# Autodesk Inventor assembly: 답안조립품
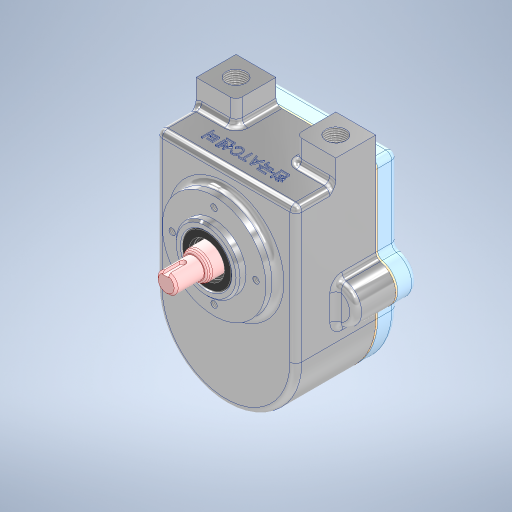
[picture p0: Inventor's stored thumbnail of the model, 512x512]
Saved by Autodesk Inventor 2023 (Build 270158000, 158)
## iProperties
Created: 2024-03
Part Number: 답안조립품
Document SubType Name: Assembly
Designer: asung
Author: asung
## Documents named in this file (9)
- C:\Users\asung\Desktop\740304V1002\답안조립품.iam
- C:\Users\asung\Desktop\740304V1002\740304V1002\본체.ipt
- C:\Users\asung\Desktop\740304V1002\740304V1002\커버.ipt
- C:\Users\asung\Desktop\740304V1002\740304V1002\가스켓.ipt
- C:\Users\asung\Desktop\740304V1002\740304V1002\오일레스 부시.ipt
- C:\Users\asung\Desktop\740304V1002\740304V1002\구동기어.ipt
- C:\Users\asung\Desktop\740304V1002\740304V1002\스퍼기어.ipt
- C:\Users\asung\Desktop\740304V1002\740304V1002\오일 실 14 25 7.ipt
- C:\Users\asung\Desktop\740304V1002\740304V1002\육각 소켓 머리 볼트 M5x12.ipt
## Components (2 placed, 2 different names)
1. 가스켓:1
2. 구동기어:1
